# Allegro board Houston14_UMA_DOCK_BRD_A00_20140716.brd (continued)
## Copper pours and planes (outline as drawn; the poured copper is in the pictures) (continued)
+DC_IN on BOTTOM (solid shape): 58.2,92.08 58.2,89.47 57.89,89.16 54.66,89.16 53.82,88.32 53.82,86.36 53.8,86.34 53.58,86.23 53.48,86.02 53.25,85.79 51.33,85.79 51.09,86.03 51.09,91.01 52.12,92.04 57.2,92.04 57.37,92.2 58.08,92.2
+DC_IN_SS on BOTTOM (solid shape): 66.08,99.57 66.08,96.14 65.82,95.89 62.59,95.89 61.25,94.55 61.25,90.36 61.19,90.3 58.65,90.3 58.52,90.43 58.52,92.78 57.89,93.41 57.89,96.14 59.58,97.83 59.59,97.83 59.77,98.01 59.77,99.65 59.93,99.81 65.84,99.81
+DCIN on TOP (solid shape): 83.26,83.14 83.26,79.86 83.13,79.73 82.19,79.73 80.96,78.5 80.19,78.5 80.09,78.6 80.09,79 81.85,80.76 81.85,83.2 81.96,83.31 83.1,83.31
+DCIN_JACK on TOP (solid shape): 45.16,92.74 45.16,89.72 45.39,89.5 45.39,88.12 44.89,87.62 43.37,87.62 43.09,87.9 43.09,92.65 43.35,92.9 45,92.9
+DCIN_JACK on BOTTOM (solid shape): 47.22,91.02 47.22,89.07 47.91,88.38 49.39,88.38 49.63,88.14 49.63,86.24 49.23,85.83 45.28,85.83 45,86.11 44.11,86.11 43.79,86.43 43.79,90.87 44.03,91.11 47.13,91.11
+DOCK_PWR_BAR on TOP (solid shape): outline of 231 points within 174.6,109.1 186.98,116.78
+DOCK_PWR_BAR on TOP (solid shape): outline of 317 points within 135.61,108.87 147.87,120.46
+DOCK_PWR_BAR on BOTTOM (solid shape): outline of 354 points within 121.39,95.43 145.38,120.27
+DOCK_PWR_BAR on IN1 (solid shape): outline of 3169 points within 137.33,110.53 186.93,118.3
+DOCK_PWR_BAR on VCC: 185.31,109.41 183.15,111.57 138.57,111.57 138.09,112.06 138.09,117.94 139.08,118.94 145.35,118.94 147.13,117.16 154.75,117.16 155.76,116.14 182.9,116.14 183.4,116.65 189.92,116.65 190.54,116.04 190.54,109.9 190.05,109.41
+EDP_VDD on TOP (solid shape): 85.47,97.79 85.47,97.32 85.55,97.25 85.89,97.25 85.97,97.17 85.97,94.91 85.83,94.77 85.17,94.77 85.01,94.92 85.01,96.03 85.03,96.14 85.01,96.26 85.01,96.62 85.01,96.85 84.86,97.04 84.86,97.21 84.89,97.25 85.24,97.25 85.29,97.3 85.29,97.77 85.33,97.81 85.46,97.81
+LCDVDD on TOP (solid shape): 87.5,99.75 87.5,98.48 87.26,98.24 87.26,97.89 86.91,97.54 86.13,97.54 85.99,97.4 85.65,97.4 85.62,97.42 85.62,97.91 85.56,97.97 85.19,97.97 85.14,97.92 85.14,97.46 85.08,97.4 84.71,97.4 84.2,97.91 84.2,99.63 84.25,99.68 84.89,99.68 85.09,99.89 87.36,99.89
+LCDVDD on BOTTOM (solid shape): 87.04,101.2 87.04,99.86 87.5,99.4 87.5,98.89 87.36,98.76 86.64,98.76 86.36,99.04 86.36,99.51 86.26,99.61 86.26,101.21 86.36,101.3 86.38,101.31 86.92,101.31
+PBATT on TOP (solid shape): outline of 132 points within 113.64,77.16 130.34,99.18
+PBATT on TOP (solid shape): outline of 400 points within 74.28,13.47 97.02,43.25
+PBATT on BOTTOM (solid shape): 118.21,82.62 118.21,77.54 117.91,77.23 114.39,77.23 113.39,78.23 113.39,82.62 113.64,82.87 117.96,82.87
+PBATT on BOTTOM (solid shape): outline of 137 points within 126.66,95.4 132.63,100.5
+PBATT on BOTTOM (solid shape): outline of 296 points within 79.24,15.26 98.23,42.48
+PBATT on VCC: 94.63,37.02 93.51,38.14 93.51,53.94 110.15,70.57 110.15,74 114.34,78.19 114.34,79.97 115.21,80.84 120.2,80.84 120.69,80.35 120.69,76.41 123.23,73.87 123.23,66.47 109.26,52.5 109.26,45.89 103.8,40.43 103.8,37.89 102.93,37.02
+PCH_ASATA3PLL on TOP (solid shape): 167.2,77.33 167.2,76.27 167.15,76.26 167.05,76.23 166.97,76.17 166.9,76.14 166.83,76.17 166.34,76.17 166.31,75.68 166.33,75.58 166.23,75.52 163.22,75.52 162.8,75.94 162.8,77.38 167.14,77.38
+PCH_VCCDSW3_3 on IN3 (solid shape): outline of 118 points within 224.68,77.1 229.79,78.81
+PCH_VCCDSW3_3 on IN3 (solid shape): outline of 558 points within 172.42,39.18 189.84,51.56
+PWR_SRC on TOP (solid shape): 101.38,86.55 101.38,82.36 98.91,79.89 98.91,78.37 98.75,78.21 93.77,78.21 93.7,78.28 93.7,84.84 95.73,86.87 101.07,86.87
+PWR_SRC on TOP (solid shape): 245.28,40.19 245.28,38.86 245.21,38.8 244.64,38.8 244.64,38.23 244.45,38.23 244.45,38.8 243.81,38.8 243.81,38.23 243.62,38.23 243.62,38.8 243.05,38.8 242.79,39.07 242.79,40.2 243.01,40.43 245.03,40.43
+PWR_SRC on TOP (solid shape): 93.72,95.01 94.03,94.49 94.35,95.01 95.58,95.01 95.9,94.69 95.9,93.33 95.68,93.11 91.22,93.11 91.14,93.2 91.14,94.29 91.86,95.01
+PWR_SRC on BOTTOM (solid shape): 205.23,74.13 205.23,72.27 205.83,71.67 205.83,68.98 205.73,68.87 204.64,68.87 204.64,68.32 204.2,68.32 204.2,68.85 203.42,68.85 203.42,68.32 203.01,68.32 203.01,68.87 202.02,68.87 201.84,69.05 201.84,71.51 201.85,71.54 201.85,72.48 203.1,73.74 203.4,73.74 203.93,74.27 205.08,74.27
+PWR_SRC on BOTTOM (solid shape): 225.62,50.61 225.62,47.2 225.13,46.71 225.13,43.61 224.78,43.27 223.56,43.27 223.56,43.44 223.18,43.82 222.8,43.44 222.8,43.27 222.59,43.27 222.19,43.67 222.19,49.32 221.53,49.98 220.45,49.98 220.32,50.1 220.32,50.68 219.81,50.68 219.81,50.87 220.32,50.87 220.32,51.5 219.81,51.5 219.81,51.69 220.32,51.69 220.32,52.2 220.38,52.26 223.96,52.26
+PWR_SRC on BOTTOM (solid shape): outline of 134 points within 93.38,76.77 114.85,93.76
+PWR_SRC on VCC (solid shape): outline of 19625 points within 93.64,37.4 246.16,105.22
+PWR_SRC_AC on TOP (solid shape): outline of 117 points within 69.3,88.17 117.82,100.23
+PWR_SRC_AC on BOTTOM (solid shape): 121.07,105.35 121.07,101.09 120.94,100.97 117.07,100.97 116.88,100.78 116.88,99.63 116.78,99.07 117.35,99.03 117.42,99.06 117.49,99.03 117.83,98.95 118.08,99.21 118.09,99.25 119.67,99.25 119.86,99.06 119.86,96.31 118.94,95.38 112.05,95.38 111.61,95.82 111.57,95.87 111.52,95.91 111.23,96.21 111.23,104.78 111.86,105.41 121.01,105.41
+PWR_SRC_AC on BOTTOM (solid shape): 73.49,100.35 73.49,100.13 72.92,99.65 73.51,99.18 73.6,99.16 73.63,99.08 73.63,95.63 73.54,95.54 72.38,95.54 72.36,95.52 72.36,94.99 71.92,94.99 71.92,95.53 71.9,95.55 71.17,95.55 71.16,95.54 71.16,95.44 71.16,95.44 71.16,94.99 70.71,94.99 70.71,95.54 70.7,95.55 69.21,95.55 68.05,96.71 68.05,98.17 67.86,98.36 67.28,98.36 67.16,98.24 67.16,96.65 67.09,96.59 66.27,96.59 66.21,96.65 66.21,99.62 66.21,100.27 66.46,100.52 73.32,100.52
+SDC_IN on BOTTOM (solid shape): 67.16,95.57 67.16,93.98 67.35,93.79 67.92,93.79 67.98,93.86 67.98,95.57 68.75,95.57 68.94,95.38 68.94,91.25 68.75,91.06 62.9,91.06 62.78,91.19 62.78,95.25 63.16,95.63 67.09,95.63
+SIM_PWR on BOTTOM (solid shape): 284.59,92.51 286.77,92.51 286.96,92.32 286.96,91.54 286.99,91.51 286.99,91.33 286.84,91.18 285.94,91.18 285.75,91.37 285.75,91.85 285.41,92.19 283.73,92.19 283.67,92.26 283.67,92.41 283.78,92.52 284.58,92.52
+SIM_PWR on BOTTOM (solid shape): 223.78,96.77 226.31,96.77 226.32,96.78 232.32,96.78 232.71,96.38 232.71,95.67 232.53,95.49 231.73,95.49 231.72,95.5 231.17,95.5 230.7,95.98 224.92,95.98 224.91,95.98 224.02,95.98 223.87,96.13 223.86,96.13 223.77,96.22 222.9,96.22 222.55,96.56 222.55,97.01 222.61,97.06 223.49,97.06
+SIM_PWR on IN2 (solid shape): 281.17,99.79 281.25,99.74 281.26,99.64 281.23,99.46 281.3,99.28 281.32,99.21 281.3,99.15 281.31,98.66 281.8,98.64 281.87,98.67 281.93,98.64 282.43,98.64 282.45,99.14 282.42,99.2 282.44,99.27 282.52,99.45 282.49,99.64 282.5,99.74 282.58,99.79 283.5,99.79 286.66,96.62 286.66,93.33 286.6,93.24 286.49,93.27 285.86,93.03 286.49,92.79 286.6,92.82 286.66,92.73 286.66,90.92 286.46,90.71 284.6,90.71 284.39,90.92 284.39,95.86 283.42,96.83 281.2,96.83 279.41,98.62 279.41,99.33 279.87,99.79
+SIM_PWR on IN3 (solid shape): 232.73,96.5 232.73,95.67 232.55,95.49 231.01,95.49 230.97,95.53 230.97,96.76 231.05,96.84 232.38,96.84
+SIM_PWR on IN3 (solid shape): 280.62,99.89 280.62,98.22 280.31,97.92 279.29,97.92 278.86,98.34 278.86,99.78 279.18,100.1 280.4,100.1
+USB_LEFT_PWR on TOP (solid shape): 63.75,105.39 63.75,103.8 62.87,102.92 62.08,102.92 62.06,102.9 62.03,102.9 61.71,102.9 61.66,102.91 61.61,102.91 60.44,102.91 60.39,102.91 60.34,102.9 60.19,102.9 60.12,102.96 60.11,103.01 60.11,105.29 60.39,105.56 63.58,105.56
+USB_LEFT_PWR on BOTTOM (solid shape): outline of 161 points within 60.24,102.75 70.51,109.6
+USB_RIGHT_PWR on BOTTOM (solid shape): 246.05,119.97 246.05,116.21 245.45,115.61 242.85,115.61 242.78,115.68 242.78,118.74 242.97,118.94 244.62,118.94 244.84,119.16 244.84,119.79 245.04,119.98 246.03,119.98
+USB_RIGHT_PWR on IN3 (solid shape): outline of 139 points within 236.16,106.1 246.2,118.34
+V_DDR_REF on BOTTOM (solid shape): 259.32,40.78 259.32,40.2 259.37,40.15 259.37,38.22 259.32,38.17 259.17,38.17 259.17,39.08 258.67,39.58 258.67,40.59 258.64,40.63 258.64,40.73 258.71,40.81 259.3,40.81
+VCHGR on TOP (solid shape): 111.23,84.52 114.27,84.52 114.47,84.33 114.47,83.51 113.2,82.24 113.2,78.43 113,78.23 105.77,78.23 105.32,78.68 105.32,82.24 107.38,82.24 107.38,82.18 107.39,82.12 107.41,82.07 107.44,82.02 107.47,81.98 107.52,81.94 107.56,81.91 107.61,81.88 107.66,81.87 107.72,81.86 107.77,81.85 107.83,81.86 107.88,81.87 107.93,81.9 107.98,81.92 108.02,81.96 108.06,82 108.09,82.05 108.12,82.1 108.13,82.15 108.14,82.21 108.14,82.26 108.13,82.32 108.12,82.37 108.09,82.42 108.06,82.47 108.02,82.51 107.98,82.55 107.93,82.57 107.88,82.6 107.83,82.61 107.77,82.62 107.72,82.61 107.66,82.6 107.61,82.59 107.56,82.56 107.52,82.53 107.47,82.49 107.44,82.45 107.41,82.4 107.39,82.35 107.38,82.29 107.38,82.24 105.32,82.24 105.32,84.58 105.58,84.84 110.85,84.84 110.85,84.84 110.91,84.84
+VCHGR on BOTTOM (solid shape): 111.21,84.53 113,84.53 113.3,84.84 114.91,84.84 115.04,84.71 115.04,83.25 114.85,83.06 113.13,83.06 112.69,82.62 112.69,77.79 112.05,77.16 103.54,77.16 103.42,77.28 103.42,77.79 103.48,77.85 105,77.85 105.19,78.04 105.19,78.55 105,78.74 103.48,78.74 103.42,78.81 103.42,80.2 105,81.79 109.96,81.79 110.21,82.04 110.21,84.71 110.34,84.84 110.91,84.84
+VHDMI_VCC on TOP (solid shape): 94.97,111.96 94.97,111.09 94.97,111.09 94.97,111 96.82,109.15 96.82,107.05 97.59,106.29 97.59,105.22 97.53,105.16 96.32,105.16 96.19,105.29 96.19,106.29 95.81,106.67 95.81,108 95.24,108.57 95.24,109.73 94.35,110.62 93.51,110.62 93.37,110.75 93.37,111.96 93.55,112.14 94.79,112.14
+VLDOIN_1.35V on BOTTOM (solid shape): 254.55,38.29 255.05,38.29 255.05,38.85 255.36,38.85 255.38,38.83 255.38,38.06 255.56,37.89 256.55,37.89 256.91,37.53 257.67,37.53 257.72,37.48 257.72,37.38 257.67,37.33 256.33,37.33 256.07,37.58 256.04,37.58 256.02,37.61 254.29,37.61 254.19,37.71 254.19,38.83 254.22,38.85 254.55,38.85
-DCIN_JACK on BOTTOM (solid shape): 43.27,91.03 43.27,86.72 43.05,86.5 41.52,86.5 41.52,85.99 41.14,85.99 41.14,86.45 41.1,86.48 40.32,86.48 40.32,85.97 39.94,85.97 39.94,86.47 39.19,86.47 39.03,86.63 39.03,90.13 39.99,91.1 43.2,91.1
AUD_HP_NB_SENSE on IN2 (solid shape): 10.45,91.06 10.45,89.73 10.26,89.54 8.67,89.54 8.55,89.66 8.55,91.06 8.74,91.25 10.26,91.25
AUD_HP_OUT_R1 on TOP (solid shape): 7.85,90.81 7.85,89.79 7.66,89.6 6.07,89.6 5.88,89.79 5.88,90.8 5.94,90.86 7.79,90.86
BOOT_1.35V on BOTTOM (solid shape): 256.32,37.15 257.72,37.15 257.78,37.09 257.78,36.96 257.72,36.9 255.82,36.9 255.31,36.39 254.65,36.39 254.6,36.44 254.6,37.38 254.67,37.45 256.02,37.45
BOOT_1.35V_C on BOTTOM (solid shape): 254.34,37.33 254.34,36.21 254.42,36.13 254.42,34.55 254.36,34.48 253.53,34.48 253.47,34.55 253.47,36.22 253.23,36.46 253.23,37.38 253.3,37.45 254.22,37.45
BST_3V on TOP (solid shape): 217.92,67.5 217.92,66.87 218.12,66.66 218.12,64.91 218.07,64.86 217.97,64.86 217.92,64.91 217.92,65.85 217.84,65.93 217.84,65.93 217.39,66.39 217.39,66.39 216.98,66.79 216.98,67.48 217.03,67.53 217.89,67.53
BST_3V_C on TOP (solid shape): 219.24,68.9 219.24,68.34 219.16,68.27 217,68.27 216.95,68.32 216.95,68.9 217.08,69.03 219.11,69.03
BST_5V on TOP (solid shape): 218.12,62.78 218.12,60.57 218.3,60.39 218.3,59.76 218.29,59.74 217.39,59.74 217.34,59.79 217.34,61.01 217.53,61.21 217.53,61.54 217.87,61.87 217.87,61.94 217.92,61.99 217.92,62.8 217.94,62.83 218.07,62.83
BST_5V_C on TOP (solid shape): 219.62,58.99 219.62,58.36 219.49,58.23 217.46,58.23 217.34,58.36 217.34,58.99 217.46,59.12 219.49,59.12
BST_+V1.05SP on TOP (solid shape): 218.95,48.36 218.95,48.22 218.93,48.12 218.95,48.02 218.95,45.91 218.88,45.85 218.06,45.85 217.88,46.03 217.88,48.44 218.02,48.58 218.73,48.58
BST_+V1.05SP on BOTTOM (solid shape): 218.39,46.48 219.02,46.48 219.05,46.46 219.05,45.75 218.96,45.66 218.2,45.66 217.94,45.91 217.16,45.91 217.04,46.03 217.04,46.56 217.14,46.66 218.21,46.66
CD3301_DCIN on BOTTOM (solid shape): 98.82,62.32 99.21,62.32 99.22,62.32 99.35,62.3 99.48,62.32 99.49,62.32 99.81,62.32 99.91,62.22 99.91,61.31 100.52,60.7 100.52,59.63 100.5,59.6 100.32,59.6 100.29,59.63 100.29,60.31 99.23,61.38 97.14,61.38 97.04,61.48 97.04,62.55 97.09,62.6 98.54,62.6
CHAGER_SRC on TOP (solid shape): 78.97,88.14 79.87,88.14 81.39,86.62 81.39,85.75 81.73,85.41 84.79,85.41 84.99,85.21 84.99,83.87 84.8,83.69 83.35,83.69 83.1,83.44 82.33,83.44 82.33,83.45 81.93,83.45 80.72,84.65 77.44,84.65 72.11,89.98 71.35,89.98 70.9,90.43 70.9,92.59 71.03,92.71 74.4,92.71
CHAGER_SRC on BOTTOM (solid shape): 70.56,95.36 70.56,94.81 71.33,94.81 71.33,95.34 71.36,95.37 71.71,95.37 71.73,95.35 71.73,94.81 72.52,94.81 72.52,95.33 72.56,95.36 74.46,95.36 74.65,95.18 74.65,91.4 74.11,90.86 69.82,90.86 69.57,91.11 69.57,91.19 69.38,91.38 69.38,95.19 69.58,95.39 70.52,95.39
CHAGER_SRC on BOTTOM (solid shape): outline of 108 points within 79.71,78.91 89.87,85.79
CHAGER_SRC on IN2 (solid shape): 78.97,88.14 79.87,88.14 79.88,88.13 80.8,88.13 82.38,86.55 84.71,86.55 84.96,86.3 84.96,84.19 84.59,83.82 81.63,83.82 80.8,84.65 77.44,84.65 72.11,89.98 71.35,89.98 70.9,90.43 70.9,92.59 71.03,92.71 74.4,92.71
CHG_BTS on TOP (solid shape): 83.03,77.54 83.03,76.8 82.96,76.73 82.32,76.73 82.28,76.76 82.26,76.76 81.79,77.24 81.24,77.24 81.17,77.31 80.19,77.31 80.12,77.37 80.12,77.45 80.19,77.51 81.17,77.51 81.24,77.59 82.15,77.59 82.22,77.59 82.26,77.63 82.94,77.63
CHG_BTS_C on TOP (solid shape): 85.02,79.51 85.24,79.29 85.24,76.81 85.08,76.65 83.78,76.65 83.68,76.75 83.68,77.84 84.02,78.18 84.02,79.38 84.16,79.52 85.02,79.52
CHG_LGATE on TOP (solid shape): 82.18,76.2 82.18,75.38 82.22,75.38 82.22,75.28 82.04,75.1 81.71,75.1 81.55,75.26 81.55,76.28 81.32,76.51 80.18,76.51 80.11,76.57 80.11,76.65 80.18,76.72 81.66,76.72
CHG_LGATE on BOTTOM (solid shape): 90.62,87.74 90.62,86.75 90.54,86.67 89.45,86.67 89.32,86.79 89.32,87.81 89.39,87.88 90.48,87.88
CHG_LGATE on IN2 (solid shape): 84.34,76.51 84.34,75.39 84.21,75.26 81.64,75.26 81.52,75.38 81.52,76.38 81.78,76.63 84.21,76.63
CHG_LGATE on IN2 (solid shape): 91.33,87.64 91.33,86.3 91.11,86.09 90.17,86.09 90.1,86.15 90.1,87.74 90.3,87.93 91.03,87.93
CHG_SNUB on BOTTOM (solid shape): 92.66,91.89 92.66,90.69 92.6,90.62 91.38,90.62 90.35,89.59 89.34,89.59 89.17,89.77 89.17,90.27 89.32,90.43 89.72,90.43 90.33,91.03 90.33,91.96 90.45,92.08 92.47,92.08
CHG_SW on TOP (solid shape): 83.86,79.43 83.86,78.44 83.82,78.4 83.35,78.4 83.27,78.48 81.69,78.48 81.32,78.11 80.18,78.11 80.12,78.16 80.12,78.25 80.2,78.32 81.01,78.32 82.16,79.47 83.24,79.47 83.38,79.61 83.68,79.61
CHG_SW on BOTTOM (solid shape): 92.65,89.19 92.65,88.01 93.09,87.57 95.14,87.57 95.47,87.25 95.47,82.86 90.97,82.86 90.26,83.57 85.91,83.57 85.76,83.71 85.76,86.32 85.95,86.51 89.14,86.51 89.15,86.53 90.82,86.53 91.07,86.78 91.07,87.73 90.65,88.14 90.65,89.33 90.69,89.37 92.46,89.37
CHG_SW on IN1 (solid shape): 88.24,84.86 88.24,84.17 87.97,83.91 86.74,83.91 86.65,83.99 86.65,84.67 87.05,85.07 88.03,85.07
CHG_SW on IN1 (solid shape): 84.74,80.8 84.74,78.73 84.38,78.37 83.3,78.37 83.17,78.5 83.17,80.46 83.59,80.88 84.65,80.88
CHG_UGATE on TOP (solid shape): 82.74,78.22 82.74,77.94 82.61,77.81 82.19,77.81 82.09,77.71 80.19,77.71 80.12,77.78 80.12,77.87 80.18,77.92 81.32,77.92 81.75,78.35 82.61,78.35
CHG_UGATE on BOTTOM (solid shape): 90.16,82.24 90.16,81.25 90.07,81.16 89.47,81.16 89.1,81.53 89.1,82.32 89.14,82.36 90.04,82.36
CHG_UGATE on IN1 (solid shape): 82.72,78.41 82.72,77.26 82.49,77.03 81.64,77.03 81.51,77.15 81.51,78.27 81.7,78.46 82.67,78.46
CHG_UGATE on IN1 (solid shape): 90.15,82.32 90.15,81 90.01,80.86 89.01,80.86 88.89,80.98 88.89,82.21 89.07,82.39 90.09,82.39
CORE_BOOT on BOTTOM (solid shape): 131.18,93.33 131.18,92.8 130.79,92.41 130.75,92.42 130.32,92.35 130.25,91.92 130.26,91.89 130.24,91.86 130.24,90.87 130.19,90.82 130.06,90.82 130.01,90.87 130.01,92.32 130.19,92.49 130.19,93.36 130.21,93.39 131.13,93.39
CORE_BOOT_C on BOTTOM (solid shape): 131.03,95.19 131.03,95.09 131.01,95.08 130.91,94.73 131.15,94.45 131.16,94.45 131.2,94.4 131.2,93.82 131.08,93.69 130.39,93.69 129.96,94.12 129.12,94.12 129.1,94.15 129.1,94.88 129.53,95.32 130.9,95.32
CORE_BOOT_R on BOTTOM (solid shape): 130.06,93.41 130.06,92.55 129.83,92.32 129.83,90.9 129.78,90.85 129.71,90.85 129.65,90.9 129.65,92.04 129.64,92.05 129.64,92.07 129.44,92.27 129.43,92.27 129.07,92.62 129.07,93.41 129.12,93.46 130.01,93.46
CORE_SNUB on TOP (solid shape): 123.28,87.85 123.28,86.1 123.1,85.92 120.76,85.92 120.59,86.1 120.59,86.93 120.69,87.04 121.62,87.04 121.88,87.3 121.88,87.8 122.03,87.95 123.18,87.95
CORE_SW on TOP (solid shape): 126.52,87.89 126.52,86.34 126.28,86.1 124.8,86.1 124.66,86.24 124.66,87.89 124.78,88 126.4,88
CORE_SW on BOTTOM (solid shape): 129.51,88.13 129.51,88.07 129.51,87.38 129.51,87.29 127.82,85.59 127.07,85.59 123.89,82.41 123.89,82.34 120.13,82.34 120,82.21 120,81.5 120.05,81.45 122.42,81.45 122.44,81.42 122.44,80 122.24,79.8 118.63,79.8 118.34,80.09 118.34,82.67 118.28,82.73 118.28,84.62 119.28,85.61 121.95,85.61 124.51,88.18 129.46,88.18
DH_1.35V on TOP (solid shape): 252.2,38.67 252.2,37.68 252.11,37.6 250.42,37.6 250.36,37.66 250.36,38.17 250.36,38.17 250.36,38.67 250.48,38.79 252.08,38.79
DH_1.35V on BOTTOM (solid shape): 256.65,36.72 257.75,36.72 257.77,36.69 257.77,36.54 257.72,36.49 256.71,36.49 256.15,35.93 255.54,35.93 255.41,36.06 255.41,36.31 255.42,36.32 255.44,36.32 255.44,36.34 255.87,36.77 256.6,36.77
DH_1.35V on IN1 (solid shape): 253.66,38.52 253.66,37.43 253.58,37.35 251.8,37.35 251.65,37.51 251.65,38.61 251.79,38.75 253.43,38.75
DH_1.35V on IN1 (solid shape): 256.6,36.67 256.6,36.41 255.87,35.68 254.75,35.68 254.65,35.78 254.65,36.52 254.95,36.82 256.45,36.82
DL_1.35V on TOP (solid shape): 248.7,32.26 248.7,31.18 248.64,31.12 247.5,31.12 247.37,31.24 247.37,32.2 247.5,32.32 248.5,32.32 248.64,32.32
DL_1.35V on BOTTOM (solid shape): 258.18,35.8 258.18,34.88 257.86,34.56 257.31,34.56 257.29,34.58 257.29,35.8 257.34,35.85 258.13,35.85
DL_1.35V on IN4 (solid shape): 249.47,31.92 249.47,31.1 249.36,31 247.48,31 247.38,31.1 247.38,31.94 247.46,32.02 249.36,32.02
DL_1.35V on IN4 (solid shape): 257.85,35.68 257.85,33.64 257.62,33.42 256.6,33.42 256.53,33.49 256.53,34.48 256.98,34.94 256.98,35.65 257.09,35.75 257.77,35.75
INT_SPK_L+ on TOP (solid shape): 24.1,79.96 24.1,79.12 23.91,78.93 22.62,78.93 22.53,79.02 22.53,79.93 22.61,80.01 24.06,80.01
INT_SPK_L+ on TOP (solid shape): 26.61,92.19 26.61,90.62 26.57,90.58 26.57,89.84 26.37,89.64 26.37,89.46 26.19,89.28 26.19,88.84 26.01,88.66 25.4,88.66 25.38,88.68 25.38,89.43 26.08,90.13 26.08,90.42 26.4,90.74 26.4,92.14 26.49,92.23 26.57,92.23
INT_SPK_L+ on IN1 (solid shape): 26.54,90.3 26.54,89.83 26.45,89.74 26.45,88.78 26.33,88.65 25.54,88.65 25.46,88.72 25.46,89.5 26.1,90.13 26.1,90.29 26.2,90.39 26.45,90.39
INT_SPK_L+ on IN1 (solid shape): 22.59,80.76 22.59,80.28 22.87,80 23.29,80 23.42,79.87 23.42,79.15 23.2,78.93 22.52,78.93 21.58,79.87 21.58,80.64 21.8,80.87 22.48,80.87
INT_SPK_L- on TOP (solid shape): 24.09,81.81 24.09,80.8 23.83,80.55 22.76,80.55 22.54,80.77 22.54,81.82 22.63,81.92 23.98,81.92
INT_SPK_L- on TOP (solid shape): 27.01,92.14 27.01,90.77 27.14,90.64 27.14,90.12 27.25,90.01 27.25,88.74 27.18,88.66 26.44,88.66 26.4,88.7 26.4,89.16 26.58,89.34 26.58,89.51 26.71,89.64 26.71,90.54 26.8,90.64 26.8,90.88 26.81,90.88 26.81,92.14 26.87,92.2 26.95,92.2
INT_SPK_L- on IN1 (solid shape): 24.56,81.61 24.56,80.65 24.45,80.55 23.16,80.55 23.1,80.61 23.1,80.97 23.05,81.02 23.05,81.52 23.1,81.57 23.8,81.57 23.97,81.74 24.42,81.74
INT_SPK_L- on IN1 (solid shape): 27.17,90.6 27.17,90.31 27.24,90.24 27.24,89.64 27.39,89.49 27.7,89.49 27.97,89.22 27.97,88.53 26.99,88.53 26.93,88.59 26.93,89.35 26.71,89.56 26.71,90.61 26.8,90.69 27.08,90.69
INT_SPK_R+ on TOP (solid shape): 23.15,84.58 23.85,84.58 24.04,84.39 24.04,82.86 23.82,82.63 22.6,82.63 22.39,82.84 22.39,84.52 22.47,84.6 23.13,84.6
INT_SPK_R+ on TOP (solid shape): 27.81,92.15 27.81,91.11 28,90.92 28,90.87 28.11,90.77 28.25,90.77 28.38,90.64 28.38,90.51 28.85,90.04 28.85,89.62 29.15,89.32 29.15,88.72 29.08,88.66 28.4,88.66 28.27,88.79 28.27,89.93 27.91,90.29 27.91,90.6 27.62,90.89 27.62,90.95 27.61,90.96 27.61,92.14 27.67,92.2 27.76,92.2
INT_SPK_R+ on IN4 (solid shape): 23.34,84.2 23.34,83.68 23.02,83.36 22.16,83.36 22.07,83.45 22.07,84.39 22.16,84.48 23.06,84.48
INT_SPK_R+ on IN4 (solid shape): 28.44,90.81 28.44,90.49 28.74,90.19 28.74,90.03 29.09,89.68 29.25,89.68 29.65,89.28 29.65,88.72 29.6,88.68 28.45,88.68 28.26,88.86 28.26,90.09 27.95,90.4 27.95,90.8 28.04,90.89 28.35,90.89
INT_SPK_R- on TOP (solid shape): 27.41,92.18 27.41,90.9 27.74,90.56 27.74,90.24 28.05,89.93 28.05,88.74 27.98,88.66 27.48,88.66 27.43,88.71 27.43,90.16 27.32,90.27 27.32,90.69 27.2,90.81 27.2,92.14 27.28,92.22 27.37,92.22
INT_SPK_R- on TOP (solid shape): 22.51,86.16 22.9,86.02 23.3,86.1 23.52,85.98 23.77,85.94 24.1,85.94 24.1,85.22 24,85.12 21.7,85.12 21.44,85.38 21.44,86.03 21.56,86.16
INT_SPK_R- on IN4 (solid shape): 23.47,86.07 23.47,85.37 23.16,85.07 21.73,85.07 21.6,85.19 21.6,86.11 21.74,86.25 23.29,86.25
INT_SPK_R- on IN4 (solid shape): 27.75,90.66 27.75,90.16 27.85,90.05 27.85,88.36 27.77,88.28 27.09,88.28 26.76,88.61 26.76,89.02 27.39,89.65 27.39,90.22 27.29,90.32 27.29,90.62 27.38,90.71 27.7,90.71
INT_SPKR_L+ on TOP (solid shape): 32.96,81.19 32.96,78.86 32.36,78.26 24.65,78.26 24.3,78.62 24.3,79.95 24.36,80.01 25.18,80.01 25.4,79.8 27.86,79.8 28.22,80.16 29.97,80.16 31.15,81.35 32.8,81.35
INT_SPKR_L- on TOP (solid shape): 33.06,82.49 33.06,82.11 32.8,81.85 30.94,81.85 30.8,81.85 29.99,81.04 28.18,81.04 27.72,81.5 25.53,81.5 24.93,80.9 24.36,80.9 24.3,80.97 24.3,81.89 25.01,82.6 32.94,82.6
INT_SPKR_R+ on TOP (solid shape): 31,83.94 32.75,83.94 32.96,83.73 32.96,83.28 32.79,83.11 24.42,83.11 24.3,83.24 24.3,84.08 24.36,84.14 24.93,84.14 25.26,83.81 27.51,83.81 27.51,83.82 27.83,83.82 27.93,83.91 27.94,83.92 28.19,84.05 28.38,84.26 30.67,84.26
INT_SPKR_R- on TOP (solid shape): 33.16,85.82 33.16,84.55 32.96,84.34 31.25,84.34 30.6,85 28.4,85 28.2,85.24 27.93,85.38 27.91,85.39 27.76,85.54 25.53,85.54 25.04,85.05 24.49,85.05 24.3,85.24 24.3,85.94 24.55,85.94 24.87,86.25 32.73,86.25
LG_3V on TOP (solid shape): 213.27,70.17 213.27,69.41 213.14,69.28 212.13,69.28 212,69.41 212,70.42 212.13,70.55 212.89,70.55
LG_3V on TOP (solid shape): 216.5,65.19 216.5,64.99 216.73,64.76 217.36,64.76 217.41,64.71 217.41,64.61 217.36,64.56 216.32,64.56 215.48,65.39 215.48,65.7 215.62,65.84 215.85,65.84
LG_3V on IN1 (solid shape): 214.11,69.97 214.11,69.23 214.06,69.18 212.69,69.18 212.59,69.28 212.59,70.45 212.69,70.55 213.53,70.55
LG_3V on IN1 (solid shape): 216.55,65.85 216.55,64.86 216.47,64.79 215.86,64.79 215.73,64.91 215.73,65.01 214.74,66 214.74,66.16 215.1,66.51 215.89,66.51
LG_5V on TOP (solid shape): 210.48,63.69 210.48,62.68 210.35,62.55 209.46,62.55 209.33,62.68 209.33,63.69 209.46,63.82 210.35,63.82
LG_5V on TOP (solid shape): 217.41,63.11 217.41,62.98 217.39,62.96 217.08,62.96 216.29,62.17 215.31,62.17 215.18,62.3 215.18,62.61 215.37,62.8 215.99,62.8 216.2,63.02 216.23,63.02 216.35,63.13 217.39,63.13
LG_5V on IN1 (solid shape): 210.48,63.69 210.48,62.68 210.35,62.55 209.33,62.55 209.21,62.68 209.21,63.69 209.33,63.82 210.35,63.82
LG_5V on IN1 (solid shape): 215.05,62.93 216.19,62.93 216.32,62.8 216.32,62.3 216.19,62.17 214.03,62.17 213.78,62.42 213.78,63.44 213.91,63.57 214.41,63.57
LP_EN# on TOP (solid shape): 171.62,87.51 171.62,85.31 171.48,85.17 170.74,85.17 170.48,85.42 170.48,87.49 170.65,87.66 171.46,87.66
NB_PSID on BOTTOM (solid shape): 49.17,90.92 49.17,88.84 48.94,88.61 47.99,88.61 47.44,89.17 47.44,90.87 47.69,91.12 48.97,91.12
Net_6 on BOTTOM (solid shape): 65.59,6.72 66.15,5.91 65.41,5.38 65.94,4.63 66.76,3.72 67.49,2.99 69.48,2.99 69.84,2.63 69.84,1.42 69.37,0.96 65.9,0.96 65.75,1.1 63.91,3.73 63.46,4.18 63.46,5.21 63.68,5.42 65.56,6.72
Net_7 on BOTTOM (solid shape): 84.35,13.79 84.35,12.08 82.81,10.54 82.01,10.54 80.86,11.7 80.86,12.21 79,14.07 79,15.09 78.59,15.51 78.59,15.71 79.28,16.4 79.9,17.02 80.42,17.02 80.51,17.11 81.04,17.11
PBAT_PRES#_C on BOTTOM (solid shape): 71.16,11.92 71.48,11.74 71.49,11.73 72.13,10.75 72.29,10.45 72.45,10.09 72.34,9.78 72.02,9.7 71.8,9.65 71.45,9.89 71.3,10.11 71.29,10.13 70.48,11.36 70.56,11.69 70.86,11.92 70.93,11.95
PBAT_SMBCLK_C on BOTTOM (solid shape): 73.67,13.52 73.93,13.3 74.72,12.19 74.77,11.97 74.67,11.63 74.39,11.42 73.92,11.57 73.01,12.98 73.03,13.32 73.11,13.42 73.38,13.55
PBAT_SMBDAT_C on BOTTOM (solid shape): 72.35,12.8 72.57,12.67 73.08,12 73.57,11.24 73.69,11.01 73.74,10.84 73.76,10.75 73.39,10.52 73.08,10.48 72.81,10.51 72.49,10.96 71.74,12.27 71.73,12.36 71.76,12.47 72.07,12.74 72.29,12.81
PBATT+_C on TOP (solid shape): 81.45,12.59 81.45,7.42 80.57,6.54 79.83,6.54 79.62,6.61 79.41,6.54 77.36,6.54 74.28,9.62 74.29,9.65 74.29,9.89 74.13,10.08 74.13,10.35 73.98,10.5 73.98,10.52 73.5,10.73 73.7,10.25 73.73,10.25 73.77,10.2 73.77,10.08 73.65,9.96 73.6,9.79 73.6,9.77 73.52,9.7 73.31,9.7 71.83,11.18 71.83,11.42 73.27,12.87 81.17,12.87
PBATT+_C on BOTTOM (solid shape): 78.55,15.04 78.55,13.95 80.05,12.45 80.05,7.24 79.67,6.86 75.6,6.86 75.01,7.45 75.01,7.5 75.03,7.53 75.06,7.55 75.4,7.9 75.06,8.26 75.03,8.27 75.01,8.31 75.01,12.59 74.21,13.4 74.21,13.78 74.21,13.79 74.21,14.11 76.24,16.14 77.45,16.14
REGCTL_PNP10 on TOP (solid shape): 273.46,85.82 276.21,85.82 276.24,85.79 276.24,85.65 276.21,85.63 274.64,85.63 274.63,85.62 274.31,85.62 274.31,85.63 274.05,85.63 273.77,85.35 273.77,84.52 273.52,84.27 271.49,84.27 271.25,84.51 271.25,86.67 271.36,86.78 272.49,86.78
RING2 on TOP (solid shape): 15.58,88.75 15.58,87.97 15.84,87.72 15.84,86.64 15.65,86.45 15.16,86.45 15.04,86.56 15.04,88.72 15.13,88.81 15.52,88.81
RING2 on TOP (solid shape): 22.97,95.99 23.16,95.99 23.23,95.92 23.3,95.92 23.31,95.91 24.03,95.91 24.1,95.84 24.1,95.76 24.05,95.71 23.12,95.71 23,95.83 22.88,95.83 22.87,95.84 22.26,95.84 21.95,96.15 21.45,96.15 21.31,96.29 21.31,96.85 21.34,96.88 22.09,96.88
RING2 on IN4 (solid shape): outline of 443 points within 15,87.49 24.55,97.09
RING2_R on TOP (solid shape): 17.11,87.14 17.11,86.55 16.92,86.36 16.74,86.36 16.53,86.15 16.53,84.76 16.42,84.65 15.79,84.65 15.71,84.72 15.71,86.15 16.1,86.54 16.1,87.25 16.15,87.3 16.94,87.3
RING2_R on BOTTOM (solid shape): 17.25,84.57 17.25,83.77 17.09,83.61 15.98,83.61 15.67,83.31 15.67,81.65 15.48,81.45 14.75,81.45 14.63,81.57 14.63,84.75 14.78,84.89 16.93,84.89
RING2_R on IN4 (solid shape): 15.67,82.29 15.67,79.31 14.66,78.3 4.69,78.3 3.32,79.68 3.32,80.62 3.66,80.96 5.35,80.96 5.74,80.57 5.74,79.79 5.92,79.62 13.32,79.62 14.3,80.6 14.3,82.39 14.51,82.59 15.37,82.59
SLEEVE on TOP (solid shape): 22.11,95.66 22.92,95.66 23.06,95.52 24.04,95.52 24.09,95.47 24.09,95.35 24.05,95.32 23.67,95.32 23.66,95.33 23.23,95.33 23.09,95.19 22.29,95.19 22.28,95.18 22.05,95.18 21.98,95.25 21.31,95.25 21.31,95.8 21.36,95.85 21.92,95.85
SLEEVE on BOTTOM (solid shape): 21.1,91.54 21.16,91.52 21.2,91.45 21.22,91.33 21.29,91.21 21.29,90.55 20.98,90.25 18.78,90.25 18.61,90.42 18.61,91.01 18.83,91.24 19.8,91.24 19.93,91.23 20.06,91.24 20.27,91.24 20.4,91.37 20.4,91.51 20.43,91.54
SLEEVE on IN1 (solid shape): outline of 221 points within 18.55,90.21 23.58,95.7
SLEEVE_R on BOTTOM (solid shape): 19.64,94.05 20.21,94.05 20.29,93.96 20.29,93.43 20.22,93.36 20.1,92.98 20.33,92.65 20.35,92.65 20.36,92.64 20.57,92.6 20.77,92.65 21.17,92.65 21.31,92.51 21.31,91.8 20.33,91.8 20.33,92.09 20.31,92.12 20.31,92.14 20.29,92.14 19.69,92.74 19.54,92.83 19.38,92.85 19.3,92.88 19.26,92.95 19.26,93.39 18.77,93.89 18.2,93.89 17.71,94.38 17.27,94.38 17.12,94.22 17.12,94.21 17.08,94.17 17.08,93.75 16.9,93.57 15.45,93.57 15.23,93.35 15.23,91.58 14.85,91.2 14.8,91.17 14.77,91.13 5.37,91.13 4.86,90.62 4.86,89.73 4.74,89.6 3.09,89.6 2.83,89.86 2.83,91.38 4.86,93.41 8.17,93.41 8.22,93.36 8.22,92.93 8.47,92.67 8.47,92.65 9.23,92.65 13.4,92.65 13.63,92.88 13.63,93.81 14.65,94.84 16.04,94.84 16.62,95.42 18.27,95.42
SNB_1.05V on BOTTOM (solid shape): 214.6,53.03 214.6,52.01 214.54,51.95 213.46,51.95 213.33,51.82 213.33,51.37 213.21,51.25 212.13,51.25 212,51.37 212,52.96 212.13,53.09 214.54,53.09
SNUB_1.35V on TOP (solid shape): 248.64,30.61 248.64,28.51 248.51,28.39 246.35,28.39 246.23,28.51 246.23,29.47 246.29,29.53 247.11,29.53 247.24,29.53 247.37,29.66 247.37,30.61 247.43,30.67 248.58,30.67
SNUB_3V on TOP (solid shape): 214.54,75.5 214.54,69.92 214.41,69.79 213.53,69.79 213.4,69.92 213.4,70.22 213.4,70.22 213.4,70.68 212.89,71.19 212.89,75.5 213.02,75.63 214.41,75.63
SNUB_5V on TOP (solid shape): 214.54,60.39 214.54,60.37 214.54,57.47 214.41,57.34 213.27,57.34 213.14,57.47 213.14,60.39 213.27,60.52 214.41,60.52
SW1 on TOP (solid shape): 212.51,62.04 212.51,56.71 212.13,56.33 206.16,56.33 206.03,56.45 206.03,60.77 206.16,60.9 208.06,60.9 208.19,60.77 208.19,59.12 208.32,58.99 209.54,58.99 209.64,59.1 209.64,62.07 209.74,62.17 212.38,62.17
SW1 on TOP (solid shape): 218.5,62.8 218.5,61.89 218.59,61.8 218.59,61.77 219.12,61.24 219.15,61.24 219.54,60.85 219.54,59.73 219.49,59.68 218.5,59.68 218.43,59.76 218.43,60.44 218.43,60.52 218.25,60.7 218.25,61.64 218.33,61.71 218.33,62.8 218.35,62.83 218.48,62.83
SW1 on BOTTOM (solid shape): outline of 87 points within 206.54,56.63 211.04,62.42
SW1 on IN1 (solid shape): 211.24,58.36 211.24,57.47 211.11,57.34 210.1,57.34 209.97,57.47 209.97,58.36 210.1,58.49 211.11,58.49
SW1 on IN1 (solid shape): 219.24,61.66 219.24,59.76 219.11,59.63 218.22,59.63 218.1,59.76 218.1,61.66 218.22,61.79 219.11,61.79
SW2 on TOP (solid shape): 212.64,75.5 212.64,71.06 212.51,70.93 209.72,70.93 209.46,71.19 209.46,71.82 209.21,72.08 206.92,72.08 206.79,72.2 206.79,73.44 206.79,75.5 207.05,75.76 212.38,75.76
SW2 on TOP (solid shape): 219.26,68.09 219.37,67.99 219.37,67.81 219.39,67.78 219.39,67.53 219.21,67.35 219.21,66.84 218.53,66.16 218.53,64.91 218.48,64.86 218.35,64.86 218.33,64.89 218.33,65.83 218.25,65.9 218.25,66.72 218.25,67.45 218.1,67.6 218.1,68.06 218.17,68.14 219.26,68.14
SW2 on BOTTOM (solid shape): 211.62,75.38 211.62,70.3 211.49,70.17 207.3,70.17 207.05,70.42 207.05,75.38 207.3,75.63 211.37,75.63
SW2 on IN1 (solid shape): 210.63,74.69 210.63,73.52 210.5,73.4 209.54,73.4 209.44,73.5 209.44,74.67 209.51,74.74 210.58,74.74
SW2 on IN1 (solid shape): 219.42,68.85 219.42,67.73 219.29,67.6 218.15,67.6 218.07,67.68 218.07,68.9 218.12,68.95 219.32,68.95
SW_1.35V on TOP (solid shape): 253.73,37.11 253.73,32.91 253.55,32.72 253.55,31.39 253.53,31.37 253.53,28.07 253.28,27.82 249.34,27.82 248.96,28.2 248.96,34.23 249.15,34.42 249.65,34.42 249.65,34.42 249.85,34.42 250.1,34.67 250.1,37.34 250.23,37.47 253.38,37.47
SW_1.35V on BOTTOM (solid shape): 257.72,36.26 257.72,36.18 257.67,36.13 257.09,36.13 256.81,35.85 256.81,34.74 256.53,34.46 255.08,34.46 255,34.53 255,35.65 255.13,35.78 256.17,35.78 256.2,35.8 256.71,36.31 257.67,36.31
SW_1.35V on BOTTOM (solid shape): 253.71,34.13 253.71,32.88 253.59,32.77 253.59,28.58 253.34,28.32 247.94,28.32 247.88,28.39 247.88,30.93 248.01,31.05 248.77,31.05 248.83,31.12 248.83,31.94 249.09,32.2 251.24,32.2 251.75,32.71 251.75,32.97 251.75,34.17 251.82,34.23 253.61,34.23
SW_1.35V on IN1 (solid shape): 253.83,35.22 253.83,33.77 253.73,33.67 252.59,33.67 252.51,33.75 252.51,35.12 252.69,35.3 253.76,35.3
SW_1.35V on IN1 (solid shape): 256.81,35.8 256.81,34.99 256.25,34.43 255.03,34.43 254.95,34.51 254.95,35.27 255.08,35.4 255.84,35.4 256.3,35.85 256.76,35.85
SW_+V1.05SP on TOP (solid shape): 214.74,48.46 214.74,46.79 214.72,46.77 214.72,46.76 214.54,46.59 213.04,46.59 212.98,46.65 212.98,48.22 213.28,48.52 214.68,48.52
SW_+V1.05SP on BOTTOM (solid shape): 210.59,52.94 210.59,49.51 210.83,49.27 212.95,49.27 212.99,49.23 212.99,48.61 213.08,48.52 214.22,48.52 214.29,48.58 215.43,48.58 215.49,48.52 215.49,47.37 215.43,47.31 214.1,47.31 213.08,46.29 209.65,46.29 209.46,46.48 209.46,52.96 209.52,53.03 210.5,53.03
UG_3V on TOP (solid shape): 206.67,73.38 206.67,72.33 206.54,72.2 205.57,72.2 205.41,72.37 205.41,73.38 205.49,73.47 206.58,73.47
UG_3V on TOP (solid shape): 217.72,65.88 217.72,64.89 217.67,64.84 217.47,64.84 217.46,64.84 217.41,64.89 216.8,64.89 216.8,66.21 216.85,66.26 217.34,66.26
UG_3V on IN1 (solid shape): 207.06,73.04 207.06,72.46 206.64,72.04 205.65,72.04 205.38,72.3 205.38,73.4 205.49,73.5 206.6,73.5
UG_3V on IN1 (solid shape): 217.51,66.97 217.51,65.14 217.41,65.04 216.83,65.04 216.73,65.14 216.73,66.31 216.42,66.61 216.42,67.07 216.47,67.12 217.36,67.12
UG_5V on TOP (solid shape): 209.46,60.77 209.46,59.25 209.36,59.15 208.5,59.15 208.32,59.32 208.32,60.77 208.45,60.9 209.33,60.9
UG_5V on TOP (solid shape): 217.74,62.75 217.74,61.93 217.4,61.59 217.4,61.26 217.3,61.16 216.77,61.16 216.64,61.29 216.64,62.33 217.01,62.7 217.41,62.7 217.56,62.85 217.64,62.85
UG_5V on IN1 (solid shape): 210.48,59.63 210.48,58.99 210.35,58.87 208.45,58.87 208.32,58.99 208.32,59.63 208.45,59.76 210.35,59.76
UG_5V on IN1 (solid shape): 217.42,62.25 217.42,59.9 217.27,59.76 216.62,59.76 216.42,59.96 216.42,61.98 216.78,62.33 217.34,62.33
VCT_LAN_R1 on TOP (solid shape): 273.15,87.82 273.15,87.32 274.23,86.24 276.07,86.24 276.07,86.05 273.79,86.05 272.52,87.32 272.52,87.95 273.02,87.95
N20813052 on BOTTOM (solid shape): outline of 105 points within 127.8,100.78 134.4,106.11

Small or netless copper shapes (teardrops, artwork), in the pictures only: 14 on TOP, 291 on BOTTOM, 1 on IN4

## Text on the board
Ref Des/Silkscreen Bottom: TAGE | VOL | DIMM A | DDR3L | LOW | DIMM B | H15 | H17 | HCA | WWAN | WLAN | WIGIG | BT
User.Comments: LA-A901P | ZAM70 | 2014-07-16 | Lily | 2015-07-16 | 1.0(A00) | +VCC_CORE | +1.05V_M | +PWR_SRC | +5V_ALW | +3.3V_ALW | GND
Ref Des/Silkscreen Top: M2X5 | 5 | H24 | 4 | 6 | 3 | 2 | 1
BODY_CENTER: trace Width | Width/space | Single 50ohm | Single 52ohm | no Ref | 5.7mil | 3.5mil | 4.8mil | 4mil | 4 / 3.7 | 3.5 / 3.2 | 4 / 4.2 | 4.4 / 3.6 | 3.5 / 4.2 | 4 / 5.9 | 3.7 / 11.3 | 3.2 / 6.7 | 9.5 / 6 | 9 / 4.5 | Ref | SB_1_2mm-10L(4mil 50ohm)_WithOutC_130627 | L1-TOP | L2-GND1 | L3-IN1 | L4-GND2 | L5-IN2 | L6-IN3 | L7-VCC | L8-IN4 | L9-GND3 | L10-BOT | LAYER | NAME | STACKUP: 10 LAYER | 39 ohm | 50 ohm | THICKNESS=1.2mm | 83 ohm | 85 ohm | 90 ohm | 100 ohm
DEVICE_TYPE_BOTTOM: FIGURE | SIZE | 8.0 | 10.0 | 20.0 | 28.0 | 35.0 | 39.0 | 55.0 | 94.0 | 110.0 | 126.0 | 130.0 | 150.0 | 157.0 | 40.0 | 43.0 | 63.0 | 71.0 | 98.0 | 39.0x33.0 | 45.0x37.0 | 55.0x24.0 | 67.0x28.0 | 67.0x31.0 | 69.0x39.0 | 71.0x31.0 | 75.0x37.0 | 94.0x28.0 | 100.0x31.0 | 102.0x31.0 | 112.0x39.0 | 118.0x33.0 | 67.0x43.0 | DRILL CHART: TOP to BOTTOM | ALL UNITS ARE IN MILS | TOLERANCE | +3.0/-3.0 | +2.0/-2.0 | PLATED | NON-PLATED | QTY | 5167 | 750 | 19 | 42 | 10 | 7 | 2 | 1 | 4 | 9
